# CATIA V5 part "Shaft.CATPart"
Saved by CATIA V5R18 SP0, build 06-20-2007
Part number: Part4
Bounding box of the stored display mesh (mm): x -10 to 60, y -9 to 9, z 0 to 55
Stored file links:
  D:\shriniwas\v5_r19\c16_CAT_v5r19\c16_Part\Gear Joint\Shaft.CATPart
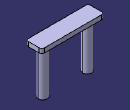
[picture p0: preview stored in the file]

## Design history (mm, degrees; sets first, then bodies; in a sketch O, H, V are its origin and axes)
Body1 (main body)
  Sketch1 on xy-plane, origin (0, 0, 0), H (1, 0, 0), V (0, 1, 0)
    circle A1 centre (0, 0) radius 5
    point P1 (30.2964, -4.0836)
    circle A2 centre (50, 0) radius 5
    point P2 (50, 0)
    radius A1 = 5
    radius A2 = 5
    distance P2 O = 50
    coincidence: P2 H
  Pad1: profile Sketch1, direction (0, 0, 1), length 50
  Sketch2 on end face of Pad1, origin (0, 0, 50), H (1, 0, 0), V (0, 1, 0)
    line L1 (-10, 9) -> (60, 9)
    line L2 (60, 9) -> (60, -9)
    line L3 (60, -9) -> (-10, -9)
    line L4 (-10, -9) -> (-10, 9)
    length L2 = 18
    distance L3 H = 9
    length L1 = 70
    distance L4 V = 10
    horizontal: L1 H, L3 H
    vertical: L2 V, L4 V
  Pad2: profile Sketch2, direction (0, 0, 1), length 5
  Fillet1: radius 3, on edge [face of Pad1 from Sketch1.A1 | start face of Pad2]; edge [face of Pad1 from Sketch1.A2 | start face of Pad2]
  Fillet2: radius 3, on edge [face of Pad2 from Sketch2.L4 | face of Pad2 from Sketch2.L1]; edge [face of Pad2 from Sketch2.L3 | face of Pad2 from Sketch2.L4]; edge [face of Pad2 from Sketch2.L1 | face of Pad2 from Sketch2.L2]; edge [face of Pad2 from Sketch2.L2 | face of Pad2 from Sketch2.L3]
